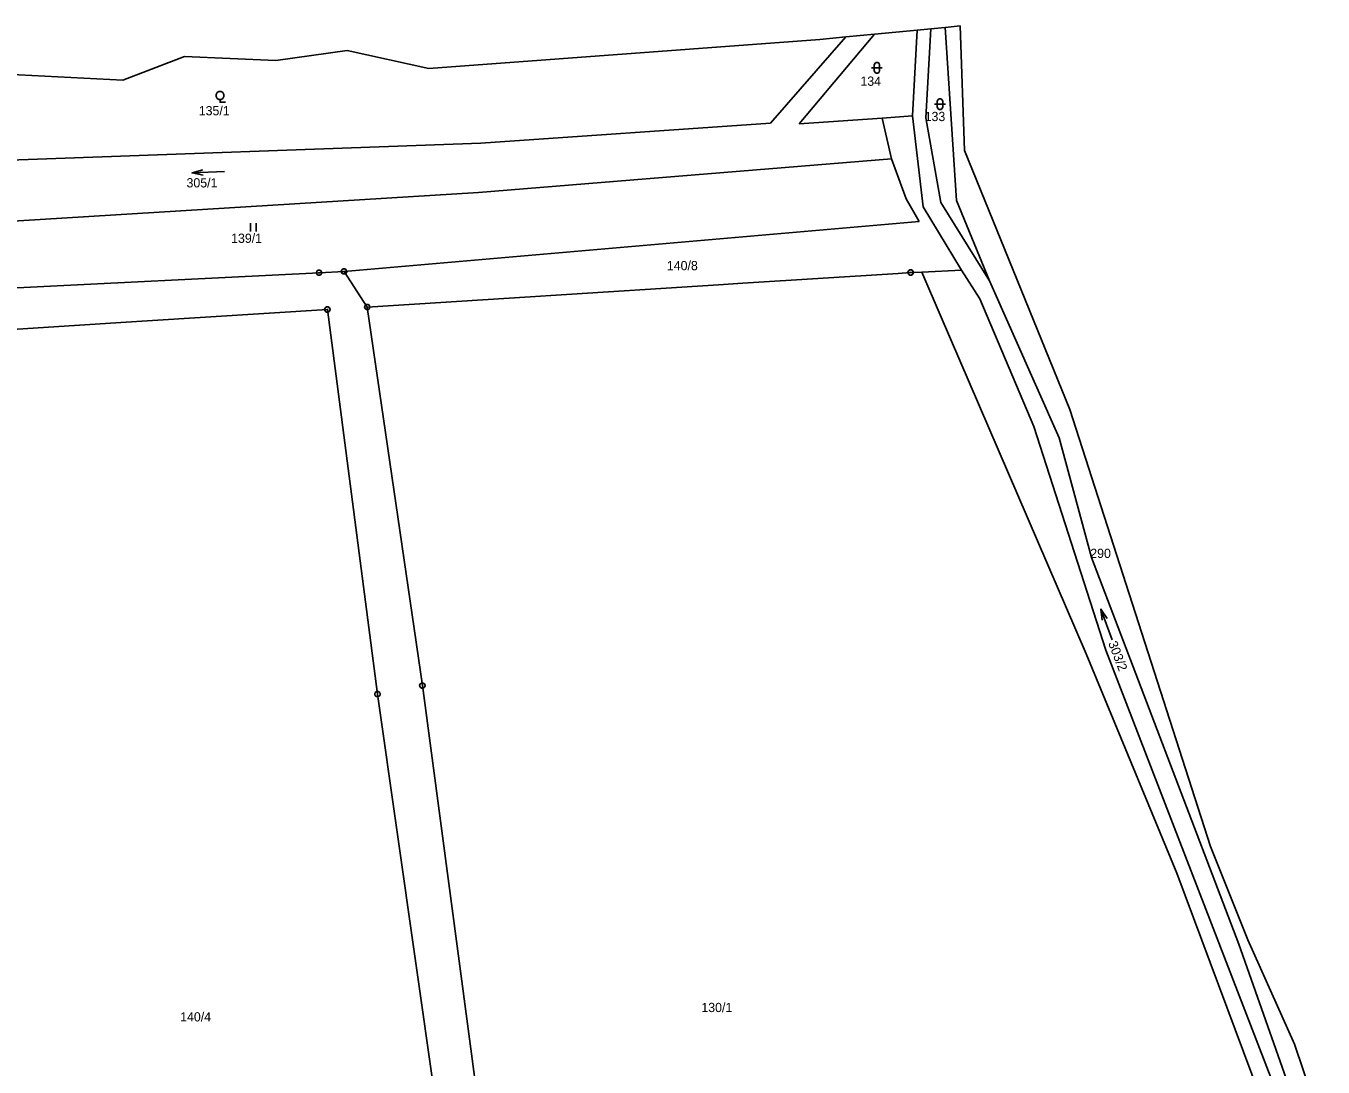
# Model space of a CAD drawing. Extents: x -779723 to -777378, y -1011169 to -1009297.
# Drawn here: x -779400.3 to -779161.8, y -1009529.1 to -1009337.8 of the extents above; entities that cross this region are included whole.
import ezdxf

# ---------------------------------------------------------------- set-up
doc = ezdxf.new("R2010")
doc.units = 0
for name, color, linetype in [('Default', 7, 'Continuous'), ('KN_HRANICE', 7, 'Continuous'), ('KN_KULTURY', 7, 'Continuous'), ('KN_PARCELY', 7, 'Continuous')]:
    doc.layers.add(name, color=color, linetype=linetype)

# ---------------------------------------------------------------- blocks, each defined once
blk = doc.blocks.new('305')
at = {"layer": 'Default'}
blk.add_lwpolyline([(0, 0.53), (-0.19, 0.53), (-0.53, 0.72), (-0.72, 1.06), (-0.72, 1.45), (-0.53, 1.79), (-0.19, 1.98), (0.2, 1.98), (0.54, 1.79), (0.73, 1.45), (0.73, 1.06), (0.54, 0.72), (0.2, 0.53), (0.01, 0.53), (0.01, 0), (1.01, 0)], dxfattribs=at)
blk = doc.blocks.new('306')
at = {"layer": 'Default'}
for p, q in [((-0.5, 1.5), (-0.5, 0)), ((0.5, 0), (0.5, 1.5))]:
    blk.add_line(p, q, dxfattribs=at)
blk = doc.blocks.new('316')
at = {"layer": 'Default'}
for points in [[(-1, 1), (0.27, 1), (1, 1)], [(-0.5, 1.5), (-0.4, 1.79), (-0.15, 1.97), (0.16, 1.97), (0.41, 1.79), (0.51, 1.5), (0.51, 0.5), (0.41, 0.21), (0.16, 0.03), (-0.15, 0.03), (-0.4, 0.21), (-0.5, 0.5), (-0.5, 1.5)]]:
    blk.add_lwpolyline(points, dxfattribs=at)
blk = doc.blocks.new('802')
at = {"layer": 'Default'}
blk.add_line((-3, 0), (3, 0), dxfattribs=at)
blk.add_lwpolyline([(1, 0.5), (3, 0), (1, -0.5)], dxfattribs=at)
blk = doc.blocks.new('105')
at = {"layer": 'Default'}
blk.add_line((-0.12, 0), (0.12, 0), dxfattribs=at)
blk.add_lwpolyline([(0.15, 0.48), (0.4, 0.3), (0.5, 0.01), (0.4, -0.28), (0.15, -0.46), (-0.16, -0.46), (-0.41, -0.28), (-0.51, 0.01), (-0.41, 0.3), (-0.16, 0.48), (0.15, 0.48)], dxfattribs=at)

msp = doc.modelspace()

# ---------------------------------------------------------------- linework, layer by layer
at = {"layer": 'KN_HRANICE'}
for p, q in [((-779233.94, -1009338.31), (-779231.28, -1009338.06)), ((-779231.28, -1009338.06), (-779228.54, -1009337.77)), ((-779229.17, -1009369.86), (-779231.28, -1009338.06)), ((-779228.54, -1009337.77), (-779227.74, -1009360.66)), ((-779326.21, -1009345.59), (-779254.3, -1009340.24)), ((-779263.37, -1009355.64), (-779249.55, -1009339.79)), ((-779258.15, -1009355.75), (-779244.29, -1009339.29)), ((-779254.3, -1009340.24), (-779249.55, -1009339.79)), ((-779249.55, -1009339.79), (-779244.29, -1009339.29)), ((-779244.29, -1009339.29), (-779236.43, -1009338.55)), ((-779237.28, -1009354.3), (-779236.43, -1009338.55)), ((-779236.43, -1009338.55), (-779233.94, -1009338.31)), ((-779233.94, -1009338.31), (-779234.82, -1009354.68)), ((-779354.35, -1009344.13), (-779341.26, -1009342.31)), ((-779341.26, -1009342.31), (-779326.21, -1009345.59)), ((-779382.46, -1009347.72), (-779371.14, -1009343.37)), ((-779371.14, -1009343.37), (-779354.35, -1009344.13)), ((-779403.99, -1009346.62), (-779382.46, -1009347.72)), ((-779242.88, -1009354.69), (-779258.15, -1009355.75)), ((-779237.28, -1009354.3), (-779242.88, -1009354.69)), ((-779242.88, -1009354.69), (-779241.15, -1009362.19)), ((-779235.31, -1009370.99), (-779237.28, -1009354.3)), ((-779234.82, -1009354.68), (-779232.07, -1009370.22)), ((-779316.63, -1009359.34), (-779263.37, -1009355.64)), ((-779404.99, -1009362.49), (-779316.63, -1009359.34)), ((-779227.74, -1009360.66), (-779208.38, -1009408.24)), ((-779241.15, -1009362.19), (-779317.11, -1009368.37)), ((-779241.15, -1009362.19), (-779238.42, -1009369.55)), ((-779317.11, -1009368.37), (-779489.81, -1009378.99)), ((-779238.42, -1009369.55), (-779236.03, -1009373.7)), ((-779228.25, -1009382.68), (-779235.31, -1009370.99)), ((-779232.07, -1009370.22), (-779223.11, -1009384.6)), ((-779223.11, -1009384.6), (-779229.17, -1009369.86)), ((-779236.03, -1009373.7), (-779341.82, -1009382.9)), ((-779346.39, -1009383.13), (-779464.1, -1009388.97)), ((-779341.82, -1009382.9), (-779346.39, -1009383.13)), ((-779341.82, -1009382.9), (-779337.54, -1009389.43)), ((-779239.91, -1009383.25), (-779268.48, -1009385.06)), ((-779237.63, -1009383.1), (-779239.91, -1009383.25)), ((-779236.97, -1009383.06), (-779237.63, -1009383.1)), ((-779235.58, -1009383), (-779236.97, -1009383.06)), ((-779228.25, -1009382.68), (-779235.58, -1009383)), ((-779232.2, -1009390.85), (-779235.58, -1009383)), ((-779224.93, -1009387.94), (-779228.25, -1009382.68)), ((-779272.95, -1009385.34), (-779303.79, -1009387.29)), ((-779268.48, -1009385.06), (-779272.95, -1009385.34)), ((-779210.32, -1009413.49), (-779223.11, -1009384.6)), ((-779307.58, -1009387.53), (-779337.54, -1009389.43)), ((-779303.79, -1009387.29), (-779307.58, -1009387.53)), ((-779214.97, -1009411.37), (-779224.93, -1009387.94)), ((-779344.87, -1009389.89), (-779377.99, -1009391.99)), ((-779335.66, -1009460.59), (-779344.87, -1009389.89)), ((-779337.54, -1009389.43), (-779327.41, -1009459.02)), ((-779381.86, -1009392.24), (-779405.87, -1009393.77)), ((-779377.99, -1009391.99), (-779381.86, -1009392.24)), ((-779205.37, -1009453.16), (-779232.2, -1009390.85)), ((-779208.38, -1009408.24), (-779182.47, -1009488.62)), ((-779201.76, -1009452.52), (-779214.97, -1009411.37)), ((-779204.35, -1009435.45), (-779210.32, -1009413.49)), ((-779177.26, -1009506.55), (-779204.35, -1009435.45)), ((-779168.29, -1009539.04), (-779201.76, -1009452.52)), ((-779205.37, -1009453.16), (-779188.66, -1009493.49)), ((-779327.41, -1009459.02), (-779314.12, -1009558.7)), ((-779321.52, -1009559.92), (-779335.66, -1009460.59)), ((-779182.47, -1009488.62), (-779175.62, -1009505.77)), ((-779171.2, -1009540.24), (-779188.66, -1009493.49)), ((-779165.16, -1009540.9), (-779177.26, -1009506.55)), ((-779175.62, -1009505.77), (-779167.06, -1009524.91)), ((-779167.06, -1009524.91), (-779161.79, -1009540.47))]:
    msp.add_line(p, q, dxfattribs=at)

# ---------------------------------------------------------------- block references
at = {"layer": 'KN_KULTURY'}
for name, p in [('316', (-779243.84, -1009346.45)), ('305', (-779364.63, -1009351.8)), ('316', (-779232.24, -1009353.15)), ('306', (-779358.49, -1009375.54))]:
    msp.add_blockref(name, p, dxfattribs=at)
for p, rotation in [((-779366.77, -1009364.64), -177.28375900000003), ((-779201.6, -1009447.78), 109.950601)]:
    msp.add_blockref('802', p, dxfattribs=dict(at, rotation=rotation))
at = {"layer": 'KN_PARCELY'}
for p in [(-779346.39, -1009383.13), (-779341.82, -1009382.9), (-779237.63, -1009383.1), (-779344.87, -1009389.89), (-779337.54, -1009389.43), (-779327.41, -1009459.02), (-779335.66, -1009460.59)]:
    msp.add_blockref('105', p, dxfattribs=at)

# ---------------------------------------------------------------- texts
for s, p in [('134', (-779246.86, -1009348.77)), ('135/1', (-779368.53, -1009354.2)), ('133', (-779235.05, -1009355.26)), ('305/1', (-779370.78, -1009367.45)), ('139/1', (-779362.58, -1009377.64)), ('140/8', (-779282.45, -1009382.67)), ('290', (-779204.6, -1009435.56)), ('140/4', (-779371.95, -1009520.75)), ('130/1', (-779276.11, -1009519.03))]:
    msp.add_text(s, height=1.7, dxfattribs=at).set_placement(p)
msp.add_text('303/2', height=1.7, rotation=291.005, dxfattribs=at).set_placement((-779201.33, -1009451.21))

doc.saveas('drawing.dxf')
